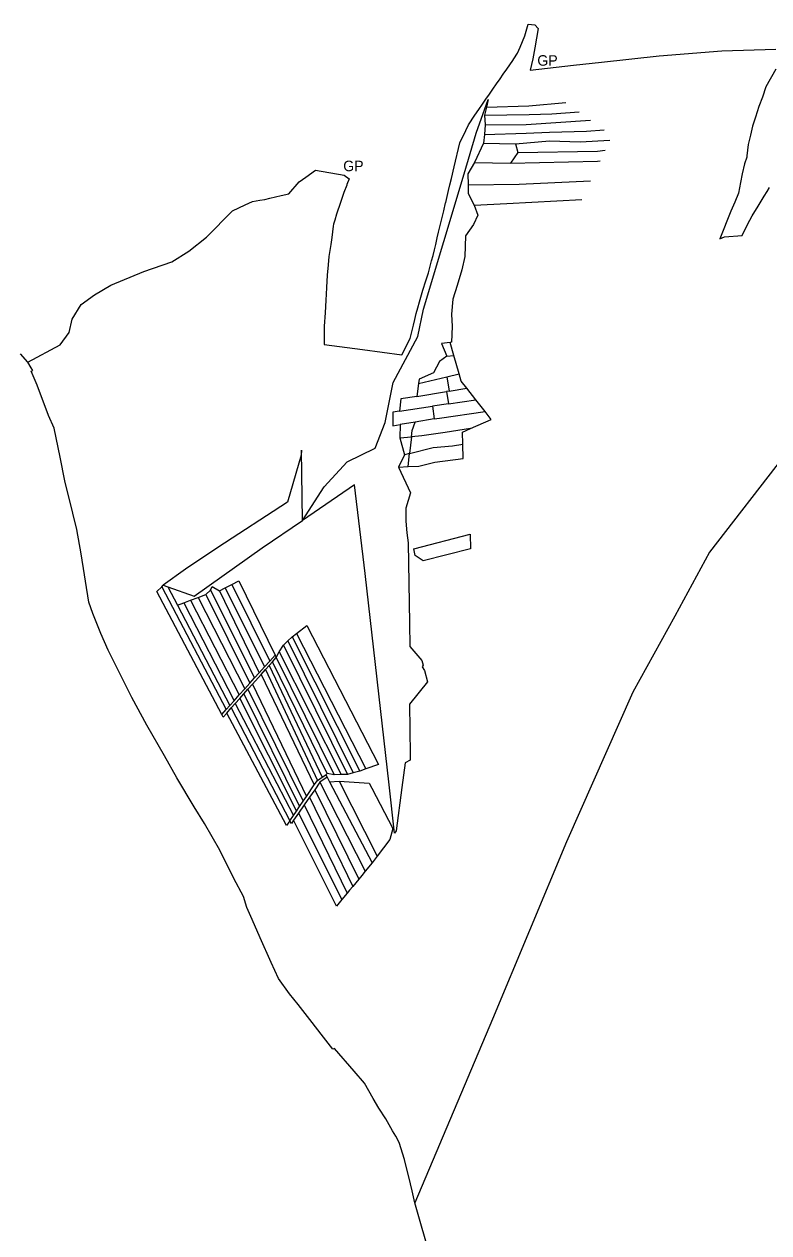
# Model space of a CAD drawing. Extents: x -534397 to -527742, y -1181460 to -1175250.
# Drawn here: x -531329 to -530722, y -1179682 to -1178695 of the extents above; entities that cross this region are included whole.
import ezdxf

# ---------------------------------------------------------------- set-up
doc = ezdxf.new("R2010")
doc.units = 0
doc.layers.add('Hranice obcí', color=7, linetype='Continuous')
doc.layers.add('Hranice parcel', color=7, linetype='Continuous')

msp = doc.modelspace()

# ---------------------------------------------------------------- linework, layer by layer
at = {"layer": 'Hranice obcí'}
for p, q in [((-530951.98, -1178763.14), (-530953.59, -1178769.64)), ((-530953.59, -1178769.64), (-530917.29, -1178769.03)), ((-530951.98, -1178763.14), (-530917.5, -1178762.04)), ((-530917.5, -1178762.04), (-530887.22, -1178759.4)), ((-530917.29, -1178769.03), (-530898.66, -1178768.72)), ((-530898.66, -1178768.72), (-530876.38, -1178767.08)), ((-530953.01, -1178777.61), (-530953.71, -1178785.42)), ((-530953.59, -1178769.64), (-530953.59, -1178769.64)), ((-530953.59, -1178769.64), (-530953.01, -1178777.61)), ((-530953.01, -1178777.61), (-530919.53, -1178777.29)), ((-530919.53, -1178777.29), (-530867.07, -1178773.68)), ((-530953.71, -1178785.42), (-530954.35, -1178792.64)), ((-530953.71, -1178785.42), (-530919.49, -1178784.46)), ((-530919.49, -1178784.46), (-530900.44, -1178783.56)), ((-530900.44, -1178783.56), (-530870.33, -1178782.72)), ((-530870.33, -1178782.72), (-530855.91, -1178781.59)), ((-530954.35, -1178792.64), (-530961.79, -1178808.42)), ((-530954.35, -1178792.64), (-530928.17, -1178793.19)), ((-530928.17, -1178793.19), (-530900.7, -1178790.7)), ((-530928.17, -1178793.19), (-530926.4, -1178800.03)), ((-530900.7, -1178790.7), (-530875.57, -1178791.48)), ((-530875.57, -1178791.48), (-530851.26, -1178790.02)), ((-530861.57, -1178799), (-530855.23, -1178798.35)), ((-530961.79, -1178808.42), (-530967.05, -1178817.49)), ((-530961.79, -1178808.42), (-530932.32, -1178808.75)), ((-530926.4, -1178800.03), (-530932.32, -1178808.75)), ((-530932.32, -1178808.75), (-530861.5, -1178807.16)), ((-530926.4, -1178800.03), (-530861.57, -1178799)), ((-530861.5, -1178807.16), (-530859.31, -1178806.92)), ((-530967.05, -1178817.49), (-530966.96, -1178826.43)), ((-530966.96, -1178826.43), (-530925.42, -1178825.87)), ((-530966.96, -1178826.43), (-530966.83, -1178833.58)), ((-530925.42, -1178825.87), (-530867.13, -1178823.34)), ((-530966.83, -1178833.58), (-530962.04, -1178843.14)), ((-530962.04, -1178843.14), (-530935.28, -1178841.79)), ((-530935.28, -1178841.79), (-530874.3, -1178838.39)), ((-530981.65, -1178955.17), (-530988.54, -1178956.07)), ((-530988.54, -1178956.07), (-530984.2, -1178966.3)), ((-530978.6, -1178965.64), (-530981.65, -1178955.17)), ((-530984.2, -1178966.3), (-530990.17, -1178970.72)), ((-530984.2, -1178966.3), (-530978.6, -1178965.64)), ((-530974.19, -1178980.8), (-530978.6, -1178965.64)), ((-530990.17, -1178970.72), (-530995.08, -1178980.05)), ((-531007.31, -1178988.72), (-530984.33, -1178983.23)), ((-531006.77, -1178984.96), (-531007.31, -1178988.72)), ((-530995.08, -1178980.05), (-531006.77, -1178984.96)), ((-530984.33, -1178983.23), (-530974.19, -1178980.8)), ((-530984.33, -1178983.23), (-530982.37, -1178994.86)), ((-530972.48, -1178986.67), (-530974.19, -1178980.8)), ((-531007.31, -1178988.72), (-531008.82, -1178999.29)), ((-531008.82, -1178999.29), (-530984.61, -1178995.23)), ((-530982.37, -1178994.86), (-530984.61, -1178995.23)), ((-530984.61, -1178995.23), (-530982.97, -1179005.27)), ((-530982.37, -1178994.86), (-530967.98, -1178992.46)), ((-530967.98, -1178992.46), (-530972.48, -1178986.67)), ((-530960.64, -1179001.9), (-530967.98, -1178992.46)), ((-531021.82, -1179001), (-531022.98, -1179011.31)), ((-531008.82, -1178999.29), (-531021.82, -1179001)), ((-530982.97, -1179005.27), (-530996.08, -1179007.25)), ((-530982.97, -1179005.27), (-530960.64, -1179001.9)), ((-530953.16, -1179011.52), (-530960.64, -1179001.9)), ((-531028.2, -1179012.05), (-531028.37, -1179023.1)), ((-531022.98, -1179011.31), (-531028.2, -1179012.05)), ((-531022.98, -1179011.31), (-530996.08, -1179007.25)), ((-530996.08, -1179007.25), (-530994.54, -1179017.58)), ((-530990.25, -1179016.88), (-530953.16, -1179011.52)), ((-530948.18, -1179017.93), (-530953.16, -1179011.52)), ((-531028.37, -1179023.1), (-531022.35, -1179022.12)), ((-531022.35, -1179022.12), (-531022.64, -1179032.84)), ((-531010.11, -1179020.12), (-531022.35, -1179022.12)), ((-531012.67, -1179026.95), (-531010.11, -1179020.12)), ((-530994.54, -1179017.58), (-531010.11, -1179020.12)), ((-530994.54, -1179017.58), (-530990.25, -1179016.88)), ((-530965.08, -1179025.36), (-530985.75, -1179028.73)), ((-530971.55, -1179028.21), (-530965.08, -1179025.36)), ((-530965.08, -1179025.36), (-530948.18, -1179017.93)), ((-531022.64, -1179032.84), (-531013.2, -1179032.05)), ((-531022.64, -1179032.84), (-531018.8, -1179046.75)), ((-531013.2, -1179032.05), (-531014.62, -1179045.67)), ((-531013.2, -1179032.05), (-531012.67, -1179026.95)), ((-531004.59, -1179031.32), (-531013.2, -1179032.05)), ((-530985.75, -1179028.73), (-531004.59, -1179031.32)), ((-530971.24, -1179038.2), (-530971.55, -1179028.21)), ((-531014.62, -1179045.67), (-530995.33, -1179040.71)), ((-530995.33, -1179040.71), (-530979.72, -1179039.57)), ((-530979.72, -1179039.57), (-530971.24, -1179038.2)), ((-530970.87, -1179049.94), (-530971.24, -1179038.2)), ((-531018.8, -1179046.75), (-531023.62, -1179056.82)), ((-531014.62, -1179045.67), (-531018.8, -1179046.75)), ((-531015.74, -1179056.43), (-531014.62, -1179045.67)), ((-531007.14, -1179056.01), (-530994.19, -1179052.94)), ((-530994.19, -1179052.94), (-530970.87, -1179049.94)), ((-531023.62, -1179056.82), (-531015.74, -1179056.43)), ((-531015.74, -1179056.43), (-531007.14, -1179056.01)), ((-531011.08, -1179123.65), (-530965.18, -1179111.67)), ((-530965.18, -1179111.67), (-530965.02, -1179123.4)), ((-531009.99, -1179129.09), (-531011.08, -1179123.65)), ((-530965.02, -1179123.4), (-531003.52, -1179133.37)), ((-531003.52, -1179133.37), (-531009.99, -1179129.09)), ((-531216.79, -1179154.42), (-531215.45, -1179153.05)), ((-531215.45, -1179153.05), (-531211.67, -1179154.43)), ((-531165.06, -1179155.43), (-531159.69, -1179152.64)), ((-531159.69, -1179152.64), (-531153.98, -1179149.66)), ((-531159.69, -1179152.64), (-531128.74, -1179215.08)), ((-531153.98, -1179149.66), (-531124.34, -1179210.16)), ((-531220.62, -1179158.33), (-531216.79, -1179154.42)), ((-531167.81, -1179258.7), (-531220.62, -1179158.33)), ((-531216.79, -1179154.42), (-531164.26, -1179254.74)), ((-531211.67, -1179154.43), (-531203.8, -1179169.49)), ((-531193.32, -1179165.53), (-531187.07, -1179163.17)), ((-531187.07, -1179163.17), (-531180.83, -1179160.82)), ((-531187.07, -1179163.17), (-531148.99, -1179237.68)), ((-531180.83, -1179160.82), (-531176.97, -1179157.26)), ((-531180.83, -1179160.82), (-531144.79, -1179232.99)), ((-531176.97, -1179157.26), (-531175.51, -1179154.23)), ((-531176.97, -1179157.26), (-531141.12, -1179228.9)), ((-531175.51, -1179154.23), (-531169.59, -1179157.74)), ((-531169.59, -1179157.74), (-531165.06, -1179155.43)), ((-531169.59, -1179157.74), (-531137.4, -1179224.74)), ((-531165.06, -1179155.43), (-531133.02, -1179219.85)), ((-531203.8, -1179169.49), (-531198.7, -1179167.56)), ((-531203.8, -1179169.49), (-531161.12, -1179251.23)), ((-531198.7, -1179167.56), (-531193.32, -1179165.53)), ((-531198.7, -1179167.56), (-531157.73, -1179247.44)), ((-531193.32, -1179165.53), (-531153.53, -1179242.75)), ((-531110.47, -1179195.22), (-531106.85, -1179192.53)), ((-531106.85, -1179192.53), (-531098.36, -1179186.19)), ((-531106.85, -1179192.53), (-531050.27, -1179303.14)), ((-531098.36, -1179186.19), (-531040.05, -1179299.41)), ((-531121.07, -1179207.5), (-531117.53, -1179202.16)), ((-531117.53, -1179202.16), (-531114, -1179198.69)), ((-531117.53, -1179202.16), (-531065.33, -1179307.53)), ((-531114, -1179198.69), (-531110.47, -1179195.22)), ((-531114, -1179198.69), (-531060.64, -1179306.33)), ((-531110.47, -1179195.22), (-531055.1, -1179304.91)), ((-531128.74, -1179215.08), (-531124.34, -1179210.16)), ((-531126.54, -1179215.71), (-531123.37, -1179212.15)), ((-531124.34, -1179210.16), (-531123.37, -1179212.15)), ((-531123.37, -1179212.15), (-531121.07, -1179207.5)), ((-531123.37, -1179212.15), (-531076.28, -1179307.84)), ((-531121.07, -1179207.5), (-531070.32, -1179307.67)), ((-531137.4, -1179224.74), (-531133.02, -1179219.85)), ((-531135.77, -1179226.08), (-531132.09, -1179221.94)), ((-531133.02, -1179219.85), (-531128.74, -1179215.08)), ((-531132.09, -1179221.94), (-531129.13, -1179218.62)), ((-531132.09, -1179221.94), (-531089.8, -1179312.43)), ((-531129.13, -1179218.62), (-531126.54, -1179215.71)), ((-531129.13, -1179218.62), (-531085.93, -1179309.76)), ((-531081.85, -1179306.94), (-531126.54, -1179215.71)), ((-531144.79, -1179232.99), (-531141.12, -1179228.9)), ((-531142.68, -1179233.86), (-531135.77, -1179226.08)), ((-531141.12, -1179228.9), (-531137.4, -1179224.74)), ((-531135.77, -1179226.08), (-531092.36, -1179316.17)), ((-531153.53, -1179242.75), (-531148.99, -1179237.68)), ((-531153.14, -1179245.61), (-531149.72, -1179241.76)), ((-531149.72, -1179241.76), (-531146.44, -1179238.08)), ((-531149.72, -1179241.76), (-531104.3, -1179333.65)), ((-531148.99, -1179237.68), (-531144.79, -1179232.99)), ((-531146.44, -1179238.08), (-531142.68, -1179233.86)), ((-531146.44, -1179238.08), (-531101.38, -1179329.37)), ((-531142.68, -1179233.86), (-531098.75, -1179325.53)), ((-531164.26, -1179254.74), (-531161.12, -1179251.23)), ((-531161.12, -1179251.23), (-531157.73, -1179247.44)), ((-531160.02, -1179253.34), (-531156.89, -1179249.82)), ((-531157.73, -1179247.44), (-531153.53, -1179242.75)), ((-531156.89, -1179249.82), (-531153.14, -1179245.61)), ((-531156.89, -1179249.82), (-531109.4, -1179341.12)), ((-531153.14, -1179245.61), (-531106.91, -1179337.47)), ((-531167.81, -1179258.7), (-531164.26, -1179254.74)), ((-531166.69, -1179260.83), (-531167.81, -1179258.7)), ((-531163.74, -1179257.51), (-531166.69, -1179260.83)), ((-531163.74, -1179257.51), (-531160.02, -1179253.34)), ((-531115.05, -1179349.38), (-531163.74, -1179257.51)), ((-531160.02, -1179253.34), (-531112.28, -1179345.33)), ((-531040.05, -1179299.41), (-531050.27, -1179303.14)), ((-531089.8, -1179312.43), (-531085.93, -1179309.76)), ((-531081.98, -1179309.86), (-531087.86, -1179313.97)), ((-531085.93, -1179309.76), (-531083.08, -1179307.79)), ((-531081.85, -1179306.94), (-531083.08, -1179307.79)), ((-531083.08, -1179307.79), (-531081.98, -1179309.86)), ((-531081.98, -1179309.86), (-531079.94, -1179313.72)), ((-531076.28, -1179307.84), (-531081.85, -1179306.94)), ((-531070.32, -1179307.67), (-531076.28, -1179307.84)), ((-531065.33, -1179307.53), (-531070.32, -1179307.67)), ((-531060.64, -1179306.33), (-531065.33, -1179307.53)), ((-531055.1, -1179304.91), (-531060.64, -1179306.33)), ((-531050.27, -1179303.14), (-531055.1, -1179304.91)), ((-531098.75, -1179325.53), (-531092.36, -1179316.17)), ((-531092.03, -1179320.02), (-531096.27, -1179326.19)), ((-531092.36, -1179316.17), (-531089.8, -1179312.43)), ((-531087.86, -1179313.97), (-531092.03, -1179320.02)), ((-531092.03, -1179320.02), (-531056.05, -1179393)), ((-531087.86, -1179313.97), (-531050.8, -1179386.64)), ((-531079.94, -1179313.72), (-531072.09, -1179313.1)), ((-531079.94, -1179313.72), (-531045.04, -1179379.66)), ((-531072.09, -1179313.1), (-531047.73, -1179314.65)), ((-531072.09, -1179313.1), (-531041.03, -1179374.29)), ((-531047.73, -1179314.65), (-531045.54, -1179318.82)), ((-531045.54, -1179318.82), (-531028.37, -1179351.58)), ((-531104.3, -1179333.65), (-531101.38, -1179329.37)), ((-531101.38, -1179329.37), (-531098.75, -1179325.53)), ((-531096.27, -1179326.19), (-531100.5, -1179332.33)), ((-531096.27, -1179326.19), (-531060.93, -1179398.92)), ((-531109.4, -1179341.12), (-531106.91, -1179337.47)), ((-531105.17, -1179339.11), (-531109.24, -1179345.03)), ((-531106.91, -1179337.47), (-531104.3, -1179333.65)), ((-531100.5, -1179332.33), (-531105.17, -1179339.11)), ((-531105.17, -1179339.11), (-531069.87, -1179409.76)), ((-531100.5, -1179332.33), (-531065.61, -1179404.59)), ((-531112.28, -1179345.33), (-531115.05, -1179349.38)), ((-531112.28, -1179345.33), (-531109.4, -1179341.12)), ((-531111.06, -1179347.67), (-531112.28, -1179345.33)), ((-531109.24, -1179345.03), (-531111.06, -1179347.67)), ((-531074.34, -1179415.18), (-531109.24, -1179345.03)), ((-531030.8, -1179360.61), (-531035.89, -1179367.41)), ((-531028.37, -1179351.58), (-531030.8, -1179360.61)), ((-531035.89, -1179367.41), (-531041.03, -1179374.29)), ((-531045.04, -1179379.66), (-531050.8, -1179386.64)), ((-531041.03, -1179374.29), (-531045.04, -1179379.66)), ((-531053.71, -1179390.16), (-531056.05, -1179393)), ((-531050.8, -1179386.64), (-531053.71, -1179390.16)), ((-531060.93, -1179398.92), (-531063.57, -1179402.12)), ((-531056.05, -1179393), (-531060.93, -1179398.92)), ((-531069.87, -1179409.76), (-531073.2, -1179413.8)), ((-531065.61, -1179404.59), (-531069.87, -1179409.76)), ((-531063.57, -1179402.12), (-531065.61, -1179404.59)), ((-531073.2, -1179413.8), (-531074.34, -1179415.18))]:
    msp.add_line(p, q, dxfattribs=at)
for points in [[(-531102.1, -1179100.35), (-531084.2, -1179072.81), (-531065.45, -1179052.51), (-531042.8, -1179041.39), (-531034.51, -1179020.32), (-531028.11, -1178987.84), (-531007.92, -1178950.32), (-531003.43, -1178928.05), (-530970.22, -1178817.6), (-530960.36, -1178784.36), (-530950.46, -1178756.99), (-530951.98, -1178763.14), (-530953.59, -1178769.64), (-530953.01, -1178777.61), (-530953.71, -1178785.42), (-530954.35, -1178792.64), (-530961.79, -1178808.42), (-530967.05, -1178817.49), (-530966.96, -1178826.43), (-530966.83, -1178833.58), (-530962.04, -1178843.14), (-530959.09, -1178851.16), (-530962.53, -1178858.85), (-530968.99, -1178868.1), (-530969.28, -1178876.57), (-530969.56, -1178884.96), (-530972.02, -1178895.92), (-530975.97, -1178908.79), (-530979.38, -1178919.9), (-530980.52, -1178932.18), (-530979.86, -1178942.02), (-530980.44, -1178955.01), (-530981.65, -1178955.17), (-530988.54, -1178956.07), (-530984.2, -1178966.3), (-530990.17, -1178970.72), (-530995.08, -1178980.05), (-531006.77, -1178984.96), (-531007.31, -1178988.72), (-531008.82, -1178999.29), (-531021.82, -1179001), (-531022.98, -1179011.31), (-531028.2, -1179012.05), (-531028.37, -1179023.1), (-531022.35, -1179022.12), (-531022.64, -1179032.84), (-531018.8, -1179046.75), (-531023.62, -1179056.82), (-531013.86, -1179077.73), (-531017.73, -1179090.29), (-531017.82, -1179100.85), (-531016.78, -1179110.55), (-531015.93, -1179118.53), (-531014.71, -1179184.29), (-531014.36, -1179203.22), (-531004.57, -1179214.53), (-531003.54, -1179218.52), (-531004.33, -1179219.77), (-531002.45, -1179222.73), (-531000.15, -1179231.96), (-531014.86, -1179250.24), (-531014.21, -1179291.68), (-531014.14, -1179296.04), (-531018.28, -1179298.03), (-531020.95, -1179318.19), (-531025.64, -1179353.71), (-531026.25, -1179354.53), (-531026.96, -1179355.47), (-531031.41, -1179316.02), (-531050.86, -1179143.53), (-531059.7, -1179071.41)], [(-531215.45, -1179153.05), (-531211.67, -1179154.43), (-531190.4, -1179162.17), (-531134.93, -1179122.75), (-531102.1, -1179100.35), (-531102.66, -1179043.05), (-531103.01, -1179046.98), (-531114.2, -1179085.45), (-531171, -1179122.39), (-531197.41, -1179140)]]:
    msp.add_lwpolyline(points, close=True, dxfattribs=at)
at = {"layer": 'Hranice parcel'}
for p, q in [((-531325.93, -1178971.19), (-531331.88, -1178964.46)), ((-531323.24, -1178975.85), (-531325.93, -1178971.19)), ((-531321.97, -1178978.05), (-531323.24, -1178975.85)), ((-531323.23, -1178978.69), (-531321.97, -1178978.05)), ((-531318.26, -1178989.87), (-531323.23, -1178978.69)), ((-531309, -1179014.8), (-531318.26, -1178989.87)), ((-531304.37, -1179025.08), (-531309, -1179014.8)), ((-531299.63, -1179048.76), (-531304.37, -1179025.08)), ((-531295.88, -1179068.05), (-531299.63, -1179048.76)), ((-531289.28, -1179094.3), (-531295.88, -1179068.05)), ((-531285.87, -1179107.69), (-531289.28, -1179094.3)), ((-531282.35, -1179127.67), (-531285.87, -1179107.69)), ((-531276.23, -1179166.96), (-531282.35, -1179127.67)), ((-531273.06, -1179176.29), (-531276.23, -1179166.96)), ((-531266.53, -1179192.6), (-531273.06, -1179176.29)), ((-531260.47, -1179206.15), (-531266.53, -1179192.6)), ((-531255.61, -1179215.98), (-531260.47, -1179206.15)), ((-531241.06, -1179244.74), (-531255.61, -1179215.98)), ((-531228.99, -1179267.31), (-531241.06, -1179244.74)), ((-531214.6, -1179292.55), (-531228.99, -1179267.31)), ((-531204.5, -1179310.4), (-531214.6, -1179292.55)), ((-531190.24, -1179334.07), (-531204.5, -1179310.4)), ((-531181.81, -1179347.76), (-531190.24, -1179334.07)), ((-531169.45, -1179369.47), (-531181.81, -1179347.76)), ((-531157.95, -1179392.4), (-531169.45, -1179369.47)), ((-531150.1, -1179407.29), (-531157.95, -1179392.4)), ((-531147.45, -1179416.11), (-531150.1, -1179407.29)), ((-531142.94, -1179425.94), (-531147.45, -1179416.11)), ((-531136.53, -1179440.96), (-531142.94, -1179425.94)), ((-531127.43, -1179460.96), (-531136.53, -1179440.96)), ((-531121.42, -1179473.99), (-531127.43, -1179460.96)), ((-531112.67, -1179486.47), (-531121.42, -1179473.99)), ((-531105.41, -1179495.28), (-531112.67, -1179486.47)), ((-531096.03, -1179507.59), (-531105.41, -1179495.28)), ((-531084.75, -1179521.88), (-531096.03, -1179507.59)), ((-531077.19, -1179531.63), (-531084.75, -1179521.88)), ((-531075.84, -1179531.28), (-531077.19, -1179531.63)), ((-531059.92, -1179549.61), (-531075.84, -1179531.28)), ((-531051.53, -1179559.4), (-531059.92, -1179549.61)), ((-531044.23, -1179572.1), (-531051.53, -1179559.4)), ((-531039.62, -1179579.84), (-531044.23, -1179572.1)), ((-531034.09, -1179588.65), (-531039.62, -1179579.84)), ((-531028.69, -1179598.46), (-531034.09, -1179588.65)), ((-531025.87, -1179602.7), (-531028.69, -1179598.46)), ((-531023.25, -1179607.78), (-531025.87, -1179602.7)), ((-531018.77, -1179621.7), (-531023.25, -1179607.78)), ((-531013.96, -1179641.75), (-531018.77, -1179621.7)), ((-531012.6, -1179647.4), (-531013.96, -1179641.75)), ((-531010.42, -1179657.02), (-531012.6, -1179647.4)), ((-530987.01, -1179738.37), (-531010.42, -1179657.02))]:
    msp.add_line(p, q, dxfattribs=at)
for points in [[(-531325.93, -1178971.19), (-531299.61, -1178956.96), (-531292.34, -1178946.9), (-531289.84, -1178936.21), (-531282.57, -1178924.12), (-531271.58, -1178916.32), (-531258.14, -1178908.47), (-531231.4, -1178897.36), (-531208.63, -1178889.4), (-531194.61, -1178880.78), (-531180.14, -1178869.28), (-531159, -1178847.65), (-531148.66, -1178842.87), (-531142.83, -1178840.17), (-531136.87, -1178839.11), (-531132.63, -1178838.36), (-531128.58, -1178837.38), (-531119.33, -1178835.16), (-531113.14, -1178833.77), (-531104.61, -1178824.18), (-531099.22, -1178820.29), (-531091.32, -1178814.59), (-531068.13, -1178818.67), (-531064.01, -1178821.72), (-531065.75, -1178826.31), (-531065.93, -1178826.77), (-531068.23, -1178832.66), (-531071.12, -1178840.97), (-531074.27, -1178850.51), (-531075.74, -1178855.34), (-531076.73, -1178858.65), (-531076.97, -1178860.25), (-531077.49, -1178865), (-531078.16, -1178869.58), (-531078.86, -1178875.27), (-531080.39, -1178884.95), (-531081.05, -1178891.86), (-531081.86, -1178900.11), (-531082.36, -1178910.35), (-531082.77, -1178915.78), (-531082.95, -1178920.69), (-531083.18, -1178925.92), (-531083.36, -1178930.84), (-531084.28, -1178941.92), (-531084.3, -1178956.79), (-531053.05, -1178960.91), (-531021.03, -1178965.1), (-531014.1, -1178951.92), (-531011.35, -1178941.14), (-531010.31, -1178936.43), (-531009.22, -1178931.63), (-531007.99, -1178926.78), (-531006.54, -1178922), (-531003.76, -1178912.39), (-531001.37, -1178904.9), (-530999.26, -1178898.22), (-530996.71, -1178888.61), (-530995.41, -1178884.16), (-530994.36, -1178879.43), (-530993.34, -1178875.18), (-530992.1, -1178869.87), (-530990.99, -1178865.02), (-530988.68, -1178855.36), (-530986.71, -1178847.65), (-530985.26, -1178841.28), (-530985.17, -1178840.91), (-530983.99, -1178835.99), (-530982.83, -1178831.11), (-530981.79, -1178826.59), (-530980.47, -1178821.35), (-530978.29, -1178811.88), (-530973.6, -1178792.15), (-530968.88, -1178782.11), (-530966.71, -1178777.5), (-530961.42, -1178769.79), (-530958.18, -1178765.04), (-530955.2, -1178760.84), (-530952.37, -1178756.64), (-530949.48, -1178752.46), (-530946.65, -1178748.39), (-530943.66, -1178744.1), (-530940.77, -1178739.98), (-530938.34, -1178736.36), (-530935.44, -1178732.05), (-530930.6, -1178725.05), (-530929.63, -1178723.64), (-530926.72, -1178719.21), (-530924.53, -1178714.23), (-530922.52, -1178709.55), (-530920.66, -1178704.82), (-530918, -1178695.44), (-530912.63, -1178695.89), (-530909.81, -1178698.88), (-530912.43, -1178714.68), (-530914.3, -1178723.66), (-530916.23, -1178732.91), (-530880.92, -1178728.96), (-530858.04, -1178726.36), (-530811.04, -1178721.31), (-530760.05, -1178717.22), (-530715.94, -1178715.94)], [(-530716.16, -1178732.1), (-530724.24, -1178746.47), (-530726.91, -1178754.88), (-530729.82, -1178762.69), (-530732.58, -1178771.2), (-530734.98, -1178778.74), (-530736.77, -1178786), (-530738.7, -1178793.57), (-530739.56, -1178802.95), (-530739.68, -1178803.92), (-530741.61, -1178809.29), (-530743.36, -1178817.51), (-530744.75, -1178824.62), (-530746.53, -1178833.28), (-530749.47, -1178840.57), (-530752.73, -1178848.05), (-530755.85, -1178856.07), (-530758.37, -1178862.56), (-530761.61, -1178870.63), (-530757.78, -1178869.07), (-530743.44, -1178867.82), (-530739.22, -1178859.02), (-530735.22, -1178851.73), (-530730.47, -1178843.91), (-530725.42, -1178835.85), (-530723.13, -1178832.09), (-530721.15, -1178828.82)], [(-530709.4, -1179047.84), (-530770.06, -1179126.34), (-530798.46, -1179178.37), (-530832.59, -1179240.49), (-530886.78, -1179362.52), (-530947.03, -1179507.4), (-531010.42, -1179657.02)]]:
    msp.add_lwpolyline(points, dxfattribs=at)

# ---------------------------------------------------------------- texts
for p in [(-530910.49, -1178729.33), (-531068.75, -1178815.41)]:
    msp.add_text('GP', height=8.59, dxfattribs=at).set_placement(p)

doc.saveas('drawing.dxf')
